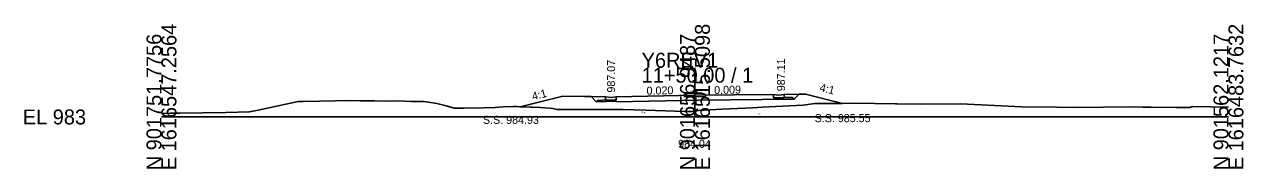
# Model space of a CAD drawing. Extents: x -26 to 203, y -10 to 2517.
# Drawn here: x -25.7 to 202.8, y 1490.3 to 1517.4 of the extents above; entities that cross this region are included whole.
import ezdxf

# ---------------------------------------------------------------- set-up
doc = ezdxf.new("R2010")
doc.units = 0
for name, color, linetype in [('Exist Cross Section Cell', 7, 'Continuous'), ('Exist XS Center Line Elevation Label', 7, 'Continuous'), ('Exist XS Ground Line', 7, 'Continuous'), ('Prop XS Dump Level', 7, 'Continuous'), ('Prop XS Earthwork Shape', 7, 'Continuous'), ('Prop XS Finish Grade CurbGutter', 7, 'Continuous'), ('Prop XS Finish Grade Earthwork', 7, 'Continuous'), ('Prop XS Finish Grade Pavement', 7, 'Continuous'), ('Prop XS Hydro Elevations', 7, 'Continuous'), ('Prop XS Pvmt Edge Slope', 7, 'Continuous'), ('Prop XS SE Text', 7, 'Continuous'), ('Prop XS Side Slope Text', 7, 'Continuous'), ('Prop XS SS Elevation Text', 7, 'Continuous'), ('Prop XS Subgrade CurbGutter', 7, 'Continuous'), ('Prop XS Subgrade Earthwork', 7, 'Continuous')]:
    doc.layers.add(name, color=color, linetype=linetype)

msp = doc.modelspace()

# ---------------------------------------------------------------- linework, layer by layer
at = {"layer": 'Exist Cross Section Cell'}
for p, q in [((100, 1500), (100, 1509.24)), ((0, 1500), (100, 1500)), ((100, 1500), (200, 1500))]:
    msp.add_line(p, q, dxfattribs=at)
at = {"layer": 'Exist XS Ground Line'}
msp.add_lwpolyline([(0, 1500.65), (1.71, 1500.71), (3.43, 1500.72), (12.04, 1500.82), (16.5, 1500.97), (18.14, 1501.28), (25.65, 1502.9), (26.59, 1502.88), (35.69, 1503.08), (37.29, 1503.05), (39.86, 1503.05), (42.88, 1502.99), (44.3, 1503.02), (46.78, 1502.92), (49.16, 1502.88), (50.04, 1502.78), (51.6, 1502.51), (53.34, 1502.08), (54.88, 1501.63), (56.7, 1501.67), (60.35, 1501.7), (62.53, 1501.8), (64.03, 1501.88), (65.93, 1501.98), (66.59, 1501.96), (71.03, 1501.79), (72.73, 1501.65), (73.37, 1501.57), (74.16, 1501.38), (75.74, 1501.4), (76.09, 1501.41), (76.79, 1501.41), (86.51, 1501.43), (90.79, 1501.27), (98.09, 1501.02), (99.84, 1501), (100.65, 1501.2), (105.06, 1501.44), (110.87, 1501.73), (112.61, 1501.84), (120.27, 1502.22), (122.47, 1502.51), (125.68, 1502.55), (129.82, 1502.56), (137.59, 1502.47), (137.93, 1502.47), (142.33, 1502.42), (149.83, 1502.47), (161.18, 1501.89), (167.77, 1501.82), (171.63, 1501.8), (181.52, 1501.88), (183.93, 1501.86), (185.48, 1501.83), (190.2, 1501.75), (192.77, 1501.79), (193.23, 1501.95), (200, 1501.87)], dxfattribs=at)
at = {"layer": 'Prop XS Earthwork Shape'}
msp.add_lwpolyline([(75.26, 1503.93), (67.26, 1501.93), (71.03, 1501.79), (72.73, 1501.65), (73.37, 1501.57), (74.16, 1501.38), (75.74, 1501.4), (76.09, 1501.41), (76.79, 1501.41), (86.51, 1501.43), (90.79, 1501.27), (98.09, 1501.02), (99.84, 1501), (100.65, 1501.2), (105.06, 1501.44), (110.87, 1501.73), (112.61, 1501.84), (120.27, 1502.22), (122.47, 1502.51), (125.68, 1502.55), (127.63, 1502.55), (120.74, 1504.28), (119.51, 1504.25), (118.6, 1503.34), (100.67, 1503.16), (85.26, 1502.85), (85.26, 1502.94), (81.51, 1502.86), (80.55, 1503.82)], close=True, dxfattribs=at)
at = {"layer": 'Prop XS Finish Grade CurbGutter'}
for p, q in [((98.07, 1504.19), (98.82, 1504.44)), ((98.07, 1504.02), (98.07, 1504.19)), ((98.82, 1504.44), (101.23, 1504.44)), ((101.98, 1504.2), (101.23, 1504.44)), ((101.98, 1504.03), (101.98, 1504.2))]:
    msp.add_line(p, q, dxfattribs=at)
at = {"layer": 'Prop XS Finish Grade Earthwork'}
for p, q in [((75.26, 1503.93), (67.26, 1501.93)), ((83.26, 1503.77), (75.26, 1503.93)), ((116.74, 1504.19), (120.74, 1504.28)), ((120.74, 1504.28), (127.63, 1502.55))]:
    msp.add_line(p, q, dxfattribs=at)
at = {"layer": 'Prop XS Finish Grade Pavement'}
for q in [(85.26, 1503.77), (114.74, 1504.19)]:
    msp.add_line((100, 1504.06), q, dxfattribs=at)
at = {"layer": 'Prop XS Pvmt Edge Slope'}
for p, q in [((81.76, 1503.12), (81.51, 1502.86)), ((82.76, 1503.14), (81.76, 1503.12)), ((117.24, 1503.66), (118.24, 1503.68)), ((118.24, 1503.68), (118.6, 1503.34))]:
    msp.add_line(p, q, dxfattribs=at)
at = {"layer": 'Prop XS Subgrade CurbGutter'}
for p, q in [((83.26, 1503.18), (83.26, 1503.77)), ((83.26, 1503.77), (84.27, 1503.68)), ((84.27, 1503.68), (85.26, 1503.77)), ((85.26, 1503.77), (85.26, 1503.19)), ((98.07, 1504.02), (98.07, 1503.77)), ((98.07, 1503.77), (101.98, 1503.85)), ((101.98, 1504.03), (101.98, 1503.85)), ((114.74, 1504.19), (114.74, 1503.61)), ((114.74, 1503.61), (114.74, 1504.19)), ((114.74, 1504.19), (115.75, 1504.11)), ((115.75, 1504.11), (116.74, 1504.19)), ((85.26, 1503.19), (82.76, 1503.14)), ((85.26, 1503.18), (83.26, 1503.18)), ((116.74, 1503.61), (114.74, 1503.61)), ((116.74, 1503.65), (117.24, 1503.66))]:
    msp.add_line(p, q, dxfattribs=at)
for points in [[(83.26, 1503.18), (85.26, 1503.18), (85.26, 1503.77)], [(114.74, 1503.61), (116.74, 1503.61), (116.74, 1504.19)]]:
    msp.add_lwpolyline(points, dxfattribs=at)
at = {"layer": 'Prop XS Subgrade Earthwork'}
for p, q in [((81.51, 1502.86), (80.55, 1503.82)), ((118.6, 1503.34), (119.51, 1504.25)), ((85.26, 1502.94), (81.51, 1502.86)), ((100.67, 1503.16), (85.26, 1502.85)), ((85.26, 1502.85), (85.26, 1502.94)), ((100.69, 1503.18), (118.6, 1503.34))]:
    msp.add_line(p, q, dxfattribs=at)

# ---------------------------------------------------------------- texts
at = {"layer": 'Exist Cross Section Cell'}
for s, p in [('N 901751.7756', (0, 1490)), ('E 1616547.2564', (2.8, 1490)), ('N 901656.9487', (100, 1490)), ('E 1616515.5098', (102.8, 1490)), ('N 901562.1217', (200, 1490)), ('E 1616483.7632', (202.8, 1490))]:
    msp.add_text(s, height=2.8, rotation=90, dxfattribs=at).set_placement(p)
for s, p in [('Y6REV1', (90, 1509.24)), ('11+50.00 / 1', (90, 1506.44)), ('EL 983', (-26, 1498.6))]:
    msp.add_text(s, height=2.8, dxfattribs=at).set_placement(p)
at = {"layer": 'Exist XS Center Line Elevation Label'}
msp.add_text('984.04', height=1.5, dxfattribs=at).set_placement((96.84, 1494.21))
msp.add_text('984.04', height=1.5, dxfattribs=at).set_placement((96.84, 1494.21))
at = {"layer": 'Prop XS Dump Level'}
for p in [(90, 1500.68), (111.69, 1500.52)]:
    msp.add_text('Eop', height=0.3, dxfattribs=at).set_placement(p)
at = {"layer": 'Prop XS Hydro Elevations'}
for s, p in [('987.07', (85.03, 1504.58)), ('987.11', (116.88, 1504.83))]:
    msp.add_text(s, height=1.5, rotation=90, dxfattribs=at).set_placement(p)
at = {"layer": 'Prop XS SE Text'}
for s, rotation, p in [('0.020', 1.1458, (90.94, 1504.17)), ('0.009', 0.7886, (103.61, 1504.32))]:
    msp.add_text(s, height=1.5, rotation=rotation, dxfattribs=at).set_placement(p)
at = {"layer": 'Prop XS Side Slope Text'}
for rotation, p in [(345.9638, (123.26, 1504.87)), (14.0362, (69.64, 1503.11))]:
    msp.add_text('4:1', height=1.5, rotation=rotation, dxfattribs=at).set_placement(p)
at = {"layer": 'Prop XS SS Elevation Text'}
for s, p in [('S.S. 984.93', (60.26, 1498.71)), ('S.S. 985.55', (122.43, 1499.03))]:
    msp.add_text(s, height=1.5, dxfattribs=at).set_placement(p)

doc.saveas('drawing.dxf')
